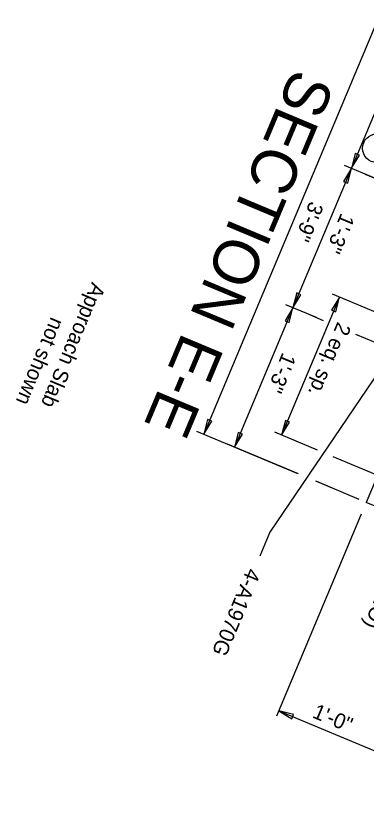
# Model space of a CAD drawing. Extents: x 1968564 to 1968711, y 796599 to 796794.
# Drawn here: x 1968641.04 to 1968652.64, y 796656.35 to 796682.8 of the extents above; entities that cross this region are included whole.
import ezdxf

# ---------------------------------------------------------------- set-up
doc = ezdxf.new("R2010")
doc.units = 0
for name, color, linetype in [('BR_AUTO DIMENSION', 7, 'Continuous'), ('BR_CONCRETE', 7, 'Continuous'), ('BR_TEXT', 7, 'Continuous')]:
    doc.layers.add(name, color=color, linetype=linetype)

msp = doc.modelspace()

# ---------------------------------------------------------------- linework, layer by layer
at = {"layer": 'BR_AUTO DIMENSION'}
for p, q in [((1968653.049, 796682.804), (1968647.247, 796668.972)), ((1968654.063, 796682.379), (1968652.129, 796677.768)), ((1968652.129, 796677.768), (1968650.195, 796673.157)), ((1968652.903, 796677.443), (1968651.899, 796677.865)), ((1968652.903, 796677.443), (1968651.899, 796677.865)), ((1968652.587, 796677.576), (1968653.134, 796677.347)), ((1968655.837, 796675.204), (1968649.435, 796665.731)), ((1968651.737, 796673.511), (1968649.821, 796668.942)), ((1968655.662, 796671.865), (1968651.507, 796673.607)), ((1968650.969, 796672.832), (1968649.965, 796673.254)), ((1968650.655, 796672.964), (1968649.965, 796673.254)), ((1968650.195, 796673.157), (1968648.261, 796668.546)), ((1968650.638, 796672.972), (1968651.2, 796672.736)), ((1968652.269, 796672.288), (1968653.22, 796671.889)), ((1968650.331, 796667.678), (1968647.017, 796669.068)), ((1968651.004, 796668.446), (1968649.591, 796669.039)), ((1968650.375, 796667.66), (1968648.031, 796668.643)), ((1968653.746, 796667.296), (1968651.527, 796668.227)), ((1968651.603, 796667.145), (1968650.955, 796667.417)), ((1968652.387, 796666.816), (1968650.98, 796667.406)), ((1968652.455, 796666.332), (1968649.654, 796659.653)), ((1968649.435, 796665.731), (1968649.103, 796664.939)), ((1968649.728, 796659.831), (1968658.028, 796656.35))]:
    msp.add_line(p, q, dxfattribs=at)
for points in [[(1968652.253, 796678.258), (1968652.129, 796677.768), (1968652.392, 796678.2)], [(1968652.005, 796677.278), (1968652.129, 796677.768), (1968651.867, 796677.336)], [(1968650.32, 796673.647), (1968650.195, 796673.157), (1968650.458, 796673.589)], [(1968651.613, 796673.021), (1968651.737, 796673.511), (1968651.475, 796673.079)], [(1968650.071, 796672.667), (1968650.195, 796673.157), (1968649.933, 796672.725)], [(1968647.372, 796669.462), (1968647.247, 796668.972), (1968647.51, 796669.404)], [(1968649.945, 796669.433), (1968649.821, 796668.942), (1968650.084, 796669.375)], [(1968648.386, 796669.036), (1968648.261, 796668.546), (1968648.524, 796668.978)], [(1968650.218, 796659.706), (1968649.728, 796659.831), (1968650.16, 796659.568)]]:
    msp.add_lwpolyline(points, close=True, dxfattribs=at)
msp.add_circle((1968652.969, 796678.429), 0.472, dxfattribs=at)
at = {"layer": 'BR_CONCRETE'}
for p in [(1968658.419, 796680.552), (1968656.306, 796665.172)]:
    msp.add_line(p, (1968652.617, 796666.719), dxfattribs=at)

# ---------------------------------------------------------------- texts
at = {"layer": 'BR_AUTO DIMENSION'}
for s, rotation, p in [('3\'-9"', 247.246, (1968650.762, 796676.706)), ('1\'-3"', 247.246, (1968651.79, 796676.313)), ('2 eq. sp.', 247.246, (1968651.675, 796672.716)), ('1\'-3"', 247.246, (1968649.856, 796671.702)), ('(UNO)', 247.246, (1968653.275, 796664.445)), ('1\'-0"', 337.246, (1968650.807, 796659.617))]:
    msp.add_text(s, height=0.5, rotation=rotation, dxfattribs=at).set_placement(p)
at = {"layer": 'BR_TEXT'}
for s, height, p in [('SECTION E-E', 1.5, (1968650.214, 796681.125)), ('Approach Slab', 0.49995, (1968643.549, 796674.026)), ('not shown', 0.4999, (1968642.199, 796672.878)), ('4-A1970G', 0.4999, (1968648.686, 796664.581))]:
    msp.add_text(s, height=height, rotation=247.246, dxfattribs=at).set_placement(p)

doc.saveas('drawing.dxf')
